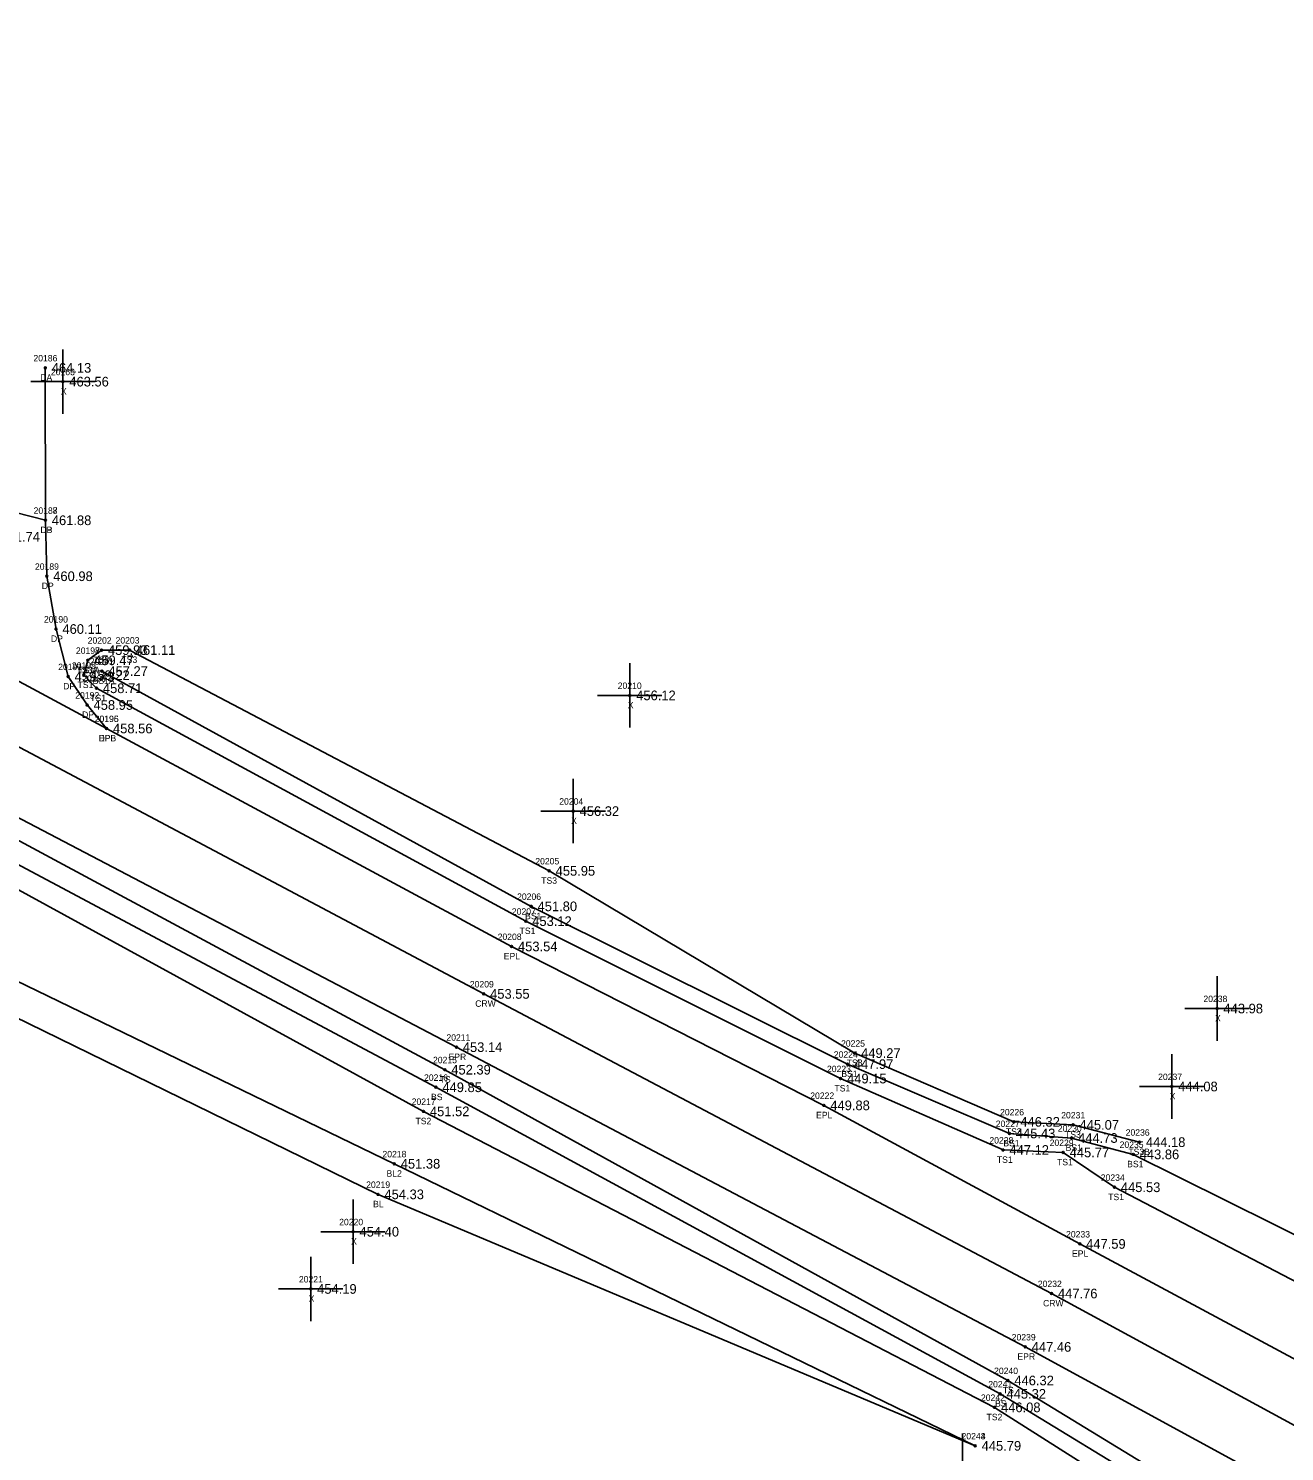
# Model space of a CAD drawing. Extents: x 1810114 to 1811498, y 790790 to 791824.
# Drawn here: x 1810337.9 to 1810533, y 791412.3 to 791633.3 of the extents above; entities that cross this region are included whole.
import ezdxf

# ---------------------------------------------------------------- set-up
doc = ezdxf.new("R2010")
doc.units = 0
for name, color, linetype in [('RD_DTM_BkLn1', 7, 'Continuous'), ('RD_DTM_BkLn2', 7, 'Continuous'), ('RD_DTM_BkLn_txCode', 7, 'Continuous'), ('RD_EX_Driveway', 7, 'Continuous'), ('RD_EX_Driveway_txCode', 7, 'Continuous'), ('RD_EX_Misc', 7, 'Continuous'), ('RD_EX_Misc_txCode', 7, 'Continuous'), ('RD_EX_Road', 7, 'Continuous'), ('RD_EX_Road_txCode', 7, 'Continuous'), ('RD_EX_TX_Driveway_ELEV', 7, 'Continuous'), ('RD_EX_TX_Misc_ELEV', 7, 'Continuous'), ('RD_EX_TX_Road_ELEV', 7, 'Continuous'), ('RD_HC_Survey_ELEV', 7, 'Continuous'), ('RD_HC_Survey_txCode', 7, 'Continuous'), ('RD_SMD_Locator', 7, 'Continuous')]:
    doc.layers.add(name, color=color, linetype=linetype)

msp = doc.modelspace()

# ---------------------------------------------------------------- linework, layer by layer
at = {"layer": 'RD_DTM_BkLn1'}
for points in [[(1810142.92, 791624.85), (1810231.36, 791577.96), (1810319.85, 791530.5), (1810408.61, 791483.38), (1810496.8, 791436.85), (1810585.08, 791388.93), (1810674.47, 791342.37), (1810763.64, 791295.68)], [(1810130.25, 791598.81), (1810215.39, 791551.2), (1810300.2, 791497.21), (1810392.2, 791452.25), (1810484.95, 791413.19)], [(1810144.18, 791597.3), (1810217.47, 791553.92), (1810302.26, 791501.79), (1810394.73, 791457), (1810484.95, 791413.19)]]:
    msp.add_lwpolyline(points, dxfattribs=at)
at = {"layer": 'RD_DTM_BkLn2'}
for points in [[(1810136.46, 791613.23), (1810225.09, 791566.55), (1810313.34, 791519.56), (1810402.58, 791471.61), (1810490.03, 791423.34), (1810516.06, 791407.46), (1810541.24, 791393.02), (1810575.56, 791368.65), (1810662.82, 791320.73), (1810730.85, 791285.33), (1810742.82, 791282.19), (1810752.34, 791280.87), (1810757.12, 791283.77)], [(1810135.37, 791610.75), (1810224.14, 791564.21), (1810311.68, 791516.56), (1810401.2, 791468.88), (1810488.81, 791421.27), (1810514.98, 791405.31), (1810539.89, 791390.39), (1810572.74, 791363.8), (1810659.47, 791316.31), (1810726.51, 791276.73), (1810738.6, 791270.6), (1810748.52, 791266.73), (1810763.99, 791268.4)], [(1810133.65, 791608.34), (1810222.15, 791560.96), (1810310.01, 791513.91), (1810399.26, 791465.14), (1810487.96, 791419.17), (1810513.17, 791403.16), (1810538.21, 791387.66)], [(1810347.12, 791535.19), (1810346.5, 791532.88), (1810348.47, 791530.85), (1810415.15, 791494.68), (1810464.05, 791470.23), (1810489.27, 791459.14), (1810498.62, 791458.76), (1810506.57, 791453.35), (1810594.61, 791407.44), (1810685.85, 791363.66), (1810698.05, 791359.62), (1810702.73, 791360.23), (1810705.69, 791363.32), (1810706.8, 791368.34), (1810706.98, 791379.45), (1810704.53, 791396.65)], [(1810347.12, 791535.19), (1810349.26, 791536.77), (1810353.59, 791536.79), (1810418.79, 791502.49), (1810466.23, 791474.19), (1810490.96, 791463.51), (1810500.15, 791463.04), (1810510.46, 791460.36)], [(1810349.32, 791533.52), (1810415.98, 791496.98), (1810465.1, 791472.47), (1810490.26, 791461.71), (1810499.93, 791461), (1810509.5, 791458.46), (1810596.77, 791415.09), (1810690.3, 791371.23), (1810701.45, 791366.46), (1810700.04, 791379.25), (1810697.34, 791395.29)]]:
    msp.add_lwpolyline(points, dxfattribs=at)
at = {"layer": 'RD_EX_Driveway'}
msp.add_line((1810340.53, 791580.61), (1810340.54, 791556.94), dxfattribs=at)
msp.add_lwpolyline([(1810316.89, 791542.45), (1810321.26, 791545.35), (1810323.84, 791547.93), (1810326.82, 791553.87), (1810328.75, 791559.98), (1810340.54, 791556.94), (1810340.76, 791548.25), (1810342.19, 791540.05), (1810344.08, 791532.67), (1810347.02, 791528.25), (1810350.04, 791524.6)], dxfattribs=at)
at = {"layer": 'RD_EX_Misc'}
for p, q in [((1810343.26, 791573.47), (1810343.26, 791583.47)), ((1810338.26, 791578.47), (1810348.26, 791578.47)), ((1810431.3, 791524.74), (1810431.3, 791534.74)), ((1810426.3, 791529.74), (1810436.3, 791529.74)), ((1810422.51, 791506.77), (1810422.51, 791516.77)), ((1810417.51, 791511.77), (1810427.51, 791511.77)), ((1810522.51, 791476.11), (1810522.51, 791486.11)), ((1810517.51, 791481.11), (1810527.51, 791481.11)), ((1810515.48, 791464), (1810515.48, 791474)), ((1810510.48, 791469), (1810520.48, 791469)), ((1810388.33, 791441.45), (1810388.33, 791451.45)), ((1810383.33, 791446.45), (1810393.33, 791446.45)), ((1810381.75, 791432.56), (1810381.75, 791442.56)), ((1810376.75, 791437.56), (1810386.75, 791437.56)), ((1810482.97, 791405.13), (1810482.97, 791415.13))]:
    msp.add_line(p, q, dxfattribs=at)
at = {"layer": 'RD_EX_Road'}
for points in [[(1810147.3, 791633.32), (1810235.73, 791586.37), (1810316.89, 791542.45), (1810324.32, 791538.42), (1810350.04, 791524.6), (1810412.94, 791490.75), (1810461.45, 791466.07), (1810501.18, 791444.55), (1810589.18, 791397.37), (1810679.08, 791351.18), (1810768.4, 791304.34)], [(1810138.18, 791616.8), (1810226.92, 791569.59), (1810315.11, 791521.87), (1810404.37, 791475.11), (1810492.73, 791428.56), (1810580.86, 791380.55), (1810670.21, 791334.43), (1810759.54, 791287.61)]]:
    msp.add_lwpolyline(points, dxfattribs=at)
at = {"layer": 'RD_SMD_Locator'}
for centre in [(1810340.53, 791580.61), (1810343.26, 791578.47), (1810340.54, 791556.94), (1810340.54, 791556.94), (1810340.76, 791548.25), (1810342.19, 791540.05), (1810347.12, 791535.19), (1810347.12, 791535.19), (1810349.26, 791536.77), (1810353.59, 791536.79), (1810344.08, 791532.67), (1810346.5, 791532.88), (1810349.32, 791533.52), (1810348.47, 791530.85), (1810347.02, 791528.25), (1810431.3, 791529.74), (1810350.04, 791524.6), (1810350.04, 791524.6), (1810422.51, 791511.77), (1810418.79, 791502.49), (1810415.98, 791496.98), (1810415.15, 791494.68), (1810412.94, 791490.75), (1810408.61, 791483.38), (1810522.51, 791481.11), (1810404.37, 791475.11), (1810466.23, 791474.19), (1810402.58, 791471.61), (1810465.1, 791472.47), (1810401.2, 791468.88), (1810464.05, 791470.23), (1810515.48, 791469), (1810399.26, 791465.14), (1810461.45, 791466.07), (1810490.26, 791461.71), (1810490.96, 791463.51), (1810500.15, 791463.04), (1810499.93, 791461), (1810510.46, 791460.36), (1810489.27, 791459.14), (1810498.62, 791458.76), (1810509.5, 791458.46), (1810394.73, 791457), (1810506.57, 791453.35), (1810392.2, 791452.25), (1810388.33, 791446.45), (1810501.18, 791444.55), (1810381.75, 791437.56), (1810496.8, 791436.85), (1810492.73, 791428.56), (1810490.03, 791423.34), (1810488.81, 791421.27), (1810487.96, 791419.17), (1810484.95, 791413.19), (1810484.95, 791413.19)]:
    msp.add_circle(centre, 0.15, dxfattribs=at)

# ---------------------------------------------------------------- texts
at = {"layer": 'RD_DTM_BkLn_txCode'}
for s, p in [('20197', (1810345.28, 791536.19)), ('20198', (1810345.28, 791536.19)), ('20202', (1810347.11, 791537.77)), ('20203', (1810351.44, 791537.79)), ('20199', (1810344.66, 791533.88)), ('20201', (1810347.44, 791534.52)), ('TS3', (1810348.02, 791534.77)), ('TS3', (1810352.35, 791534.79)), ('TS3A', (1810345.38, 791533.19)), ('TS1A', (1810345.67, 791533.19)), ('20200', (1810346.27, 791531.85)), ('BS1A', (1810347.88, 791531.52)), ('TS1', (1810345.54, 791530.88)), ('TS1', (1810347.51, 791528.85)), ('20205', (1810416.63, 791503.49)), ('TS3', (1810417.55, 791500.49)), ('20206', (1810413.8, 791497.98)), ('20207', (1810412.99, 791495.68)), ('BS1', (1810415.04, 791494.98)), ('TS1', (1810414.19, 791492.68)), ('20225', (1810464.11, 791475.19)), ('20215', (1810400.74, 791472.61)), ('20224', (1810462.99, 791473.47)), ('TS3', (1810464.99, 791472.19)), ('20216', (1810399.35, 791469.88)), ('20223', (1810461.93, 791471.23)), ('BS1', (1810464.16, 791470.47)), ('TS', (1810401.78, 791469.61)), ('TS1', (1810463.09, 791468.23)), ('20217', (1810397.43, 791466.14)), ('BS', (1810400.43, 791466.88)), ('TS2', (1810398.02, 791463.14)), ('20226', (1810488.81, 791464.51)), ('20231', (1810498.31, 791464.04)), ('20227', (1810488.14, 791462.71)), ('TS3', (1810489.71, 791461.51)), ('20230', (1810497.78, 791462)), ('TS3', (1810498.9, 791461.04)), ('20236', (1810508.32, 791461.36)), ('20228', (1810487.15, 791460.14)), ('BS1', (1810489.32, 791459.71)), ('20229', (1810496.51, 791459.76)), ('BS1', (1810498.99, 791459)), ('20235', (1810507.38, 791459.46)), ('20218', (1810392.89, 791458)), ('TS1', (1810488.31, 791457.14)), ('TS1', (1810497.66, 791456.76)), ('BS1', (1810508.55, 791456.46)), ('TS3B', (1810508.74, 791458.36)), ('BL2', (1810393.52, 791455)), ('20234', (1810504.45, 791454.35)), ('20219', (1810390.36, 791453.25)), ('BL', (1810391.44, 791450.25)), ('TS1', (1810505.61, 791451.35)), ('20240', (1810487.88, 791424.34)), ('20241', (1810486.98, 791422.27)), ('TS', (1810489.24, 791421.34)), ('20242', (1810485.84, 791420.17)), ('BS', (1810488.03, 791419.27)), ('TS2', (1810486.71, 791417.17)), ('20243', (1810482.83, 791414.19)), ('20244', (1810482.83, 791414.19))]:
    msp.add_text(s, height=1, dxfattribs=at).set_placement(p)
at = {"layer": 'RD_EX_Driveway_txCode'}
for s, p in [('20186', (1810338.68, 791581.61)), ('DA', (1810339.74, 791578.61)), ('20187', (1810338.71, 791557.94)), ('20188', (1810338.71, 791557.94)), ('DB', (1810339.76, 791554.94)), ('DP', (1810339.76, 791554.94)), ('20189', (1810338.92, 791549.25)), ('DP', (1810339.98, 791546.25)), ('20190', (1810340.32, 791541.05)), ('DP', (1810341.41, 791538.05)), ('20191', (1810342.53, 791533.67)), ('DP', (1810343.31, 791530.67)), ('20192', (1810345.18, 791529.25)), ('DP', (1810346.24, 791526.25)), ('20195', (1810348.21, 791525.6)), ('DPB', (1810348.79, 791522.6))]:
    msp.add_text(s, height=1, dxfattribs=at).set_placement(p)
at = {"layer": 'RD_EX_Misc_txCode'}
for s, p in [('20163', (1810341.4, 791579.47)), ('X', (1810342.95, 791576.47)), ('20210', (1810429.43, 791530.74)), ('X', (1810430.99, 791527.74)), ('20204', (1810420.35, 791512.77)), ('X', (1810422.2, 791509.77)), ('20238', (1810520.39, 791482.11)), ('X', (1810522.2, 791479.11)), ('20237', (1810513.36, 791470)), ('X', (1810515.16, 791467)), ('20220', (1810386.17, 791447.45)), ('X', (1810388.02, 791444.45)), ('20221', (1810379.91, 791438.56)), ('X', (1810381.43, 791435.56))]:
    msp.add_text(s, height=1, dxfattribs=at).set_placement(p)
at = {"layer": 'RD_EX_Road_txCode'}
for s, p in [('20196', (1810348.19, 791525.6)), ('EPL', (1810348.84, 791522.6)), ('20208', (1810410.78, 791491.75)), ('EPL', (1810411.73, 791488.75)), ('20211', (1810402.82, 791476.11)), ('EPR', (1810403.15, 791473.11)), ('20222', (1810459.33, 791467.07)), ('EPL', (1810460.24, 791464.07)), ('20233', (1810499.06, 791445.55)), ('EPL', (1810499.98, 791442.55)), ('20239', (1810490.62, 791429.56)), ('EPR', (1810491.51, 791426.56))]:
    msp.add_text(s, height=1, dxfattribs=at).set_placement(p)
at = {"layer": 'RD_EX_TX_Driveway_ELEV'}
for s, p in [('464.13', (1810341.53, 791579.86)), ('461.88', (1810341.54, 791556.19)), ('461.88', (1810341.54, 791556.19)), ('460.98', (1810341.76, 791547.5)), ('460.11', (1810343.19, 791539.3)), ('459.43', (1810345.08, 791531.92)), ('458.95', (1810348.02, 791527.5)), ('458.56', (1810351.04, 791523.85))]:
    msp.add_text(s, height=1.5, dxfattribs=at).set_placement(p)
at = {"layer": 'RD_EX_TX_Misc_ELEV'}
for s, p in [('463.56', (1810344.26, 791577.72)), ('461.74', (1810333.56, 791553.63)), ('459.93', (1810350.26, 791536.02)), ('461.11', (1810354.59, 791536.04)), ('459.47', (1810348.12, 791534.44)), ('459.47', (1810348.12, 791534.44)), ('459.22', (1810347.5, 791532.13)), ('457.27', (1810350.32, 791532.77)), ('458.71', (1810349.47, 791530.1)), ('456.12', (1810432.3, 791528.99)), ('456.32', (1810423.51, 791511.02)), ('455.95', (1810419.79, 791501.74)), ('451.80', (1810416.98, 791496.23)), ('453.12', (1810416.15, 791493.93)), ('443.98', (1810523.51, 791480.36)), ('447.97', (1810466.1, 791471.72)), ('449.27', (1810467.23, 791473.44)), ('452.39', (1810403.58, 791470.86)), ('449.15', (1810465.05, 791469.48)), ('449.85', (1810402.2, 791468.13)), ('444.08', (1810516.48, 791468.25)), ('451.52', (1810400.26, 791464.39)), ('446.32', (1810491.96, 791462.76)), ('445.43', (1810491.26, 791460.96)), ('445.07', (1810501.15, 791462.29)), ('447.12', (1810490.27, 791458.39)), ('444.73', (1810500.93, 791460.25)), ('444.18', (1810511.46, 791459.61)), ('451.38', (1810395.73, 791456.25)), ('445.77', (1810499.62, 791458.01)), ('443.86', (1810510.5, 791457.71)), ('454.33', (1810393.2, 791451.5)), ('445.53', (1810507.57, 791452.6)), ('454.40', (1810389.33, 791445.7)), ('454.19', (1810382.75, 791436.81)), ('445.32', (1810489.81, 791420.52)), ('446.32', (1810491.03, 791422.59)), ('446.08', (1810488.96, 791418.42)), ('445.79', (1810485.95, 791412.44)), ('445.79', (1810485.95, 791412.44))]:
    msp.add_text(s, height=1.5, dxfattribs=at).set_placement(p)
at = {"layer": 'RD_EX_TX_Road_ELEV'}
for s, p in [('458.56', (1810351.04, 791523.85)), ('453.54', (1810413.94, 791490)), ('453.14', (1810405.37, 791474.36)), ('449.88', (1810462.45, 791465.32)), ('447.59', (1810502.18, 791443.8)), ('447.46', (1810493.73, 791427.81))]:
    msp.add_text(s, height=1.5, dxfattribs=at).set_placement(p)
at = {"layer": 'RD_HC_Survey_ELEV'}
for s, p in [('453.55', (1810409.61, 791482.63)), ('447.76', (1810497.8, 791436.1))]:
    msp.add_text(s, height=1.5, dxfattribs=at).set_placement(p)
at = {"layer": 'RD_HC_Survey_txCode'}
for s, p in [('20209', (1810406.46, 791484.38)), ('CRW', (1810407.3, 791481.38)), ('20232', (1810494.68, 791437.85)), ('CRW', (1810495.49, 791434.85))]:
    msp.add_text(s, height=1, dxfattribs=at).set_placement(p)

doc.saveas('drawing.dxf')
